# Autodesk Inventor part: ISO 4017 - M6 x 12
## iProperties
Comments: To add or edit properties for Autodesk Inventor files, use iProperties.
Created: 2004-08
Part Number: ISO 4017 - M6 x 12
Vendor: Autodesk Inc.
Document SubType Name: Modeling
Designer: John Blackburn
Material: Default
Description: Hex-Head Bolt
Standard: ISO 4017
Alert: To add or edit properties for Autodesk Inventor files, use iProperties.
Control State: 0
Master: False
Checked Out: False
Shininess: 64.0
Length Units: 11269
Angle Units: 11279
Time Units: 11290
Mass Units: 11283
Length Display Precision: 3
Angle Display Precision: 2
Compacted: True
EGR: 1
Density: 0.0
Volumn: 0.0
Area: 0.0
PropertySet Name: Model Information
Author: John Blackburn
Revision Number: 8
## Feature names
1. Body [Revolution]
2. Head [Extrusion]
3. Chamfer1 [Revolution]
4. Chamfer2
